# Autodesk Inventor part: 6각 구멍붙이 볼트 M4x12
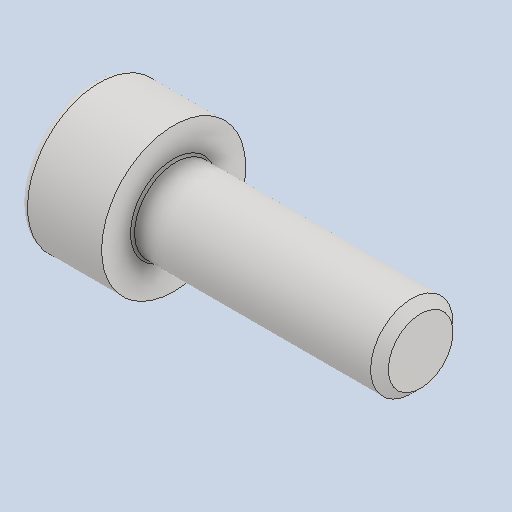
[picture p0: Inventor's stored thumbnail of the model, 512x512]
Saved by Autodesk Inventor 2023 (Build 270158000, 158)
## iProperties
Created: 2025-03
Part Number: 6각 구멍붙이 볼트 M4x12
Material: 스테인리스강
Description: 6각 소켓 머리 캡 나사
Document SubType Name: Modeling
Designer: Admin
Density: 8.08 g/cm^3
Appearance: 기본값
Author: jhkim
Sending System: Autodesk Inventor 2025
Preprocessor: ST-DEVELOPER v20
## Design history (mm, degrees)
feature "Solid1"
node "솔리드1"
